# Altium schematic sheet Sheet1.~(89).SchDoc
size A3; SheetNumber: 1; SheetTotal: 1
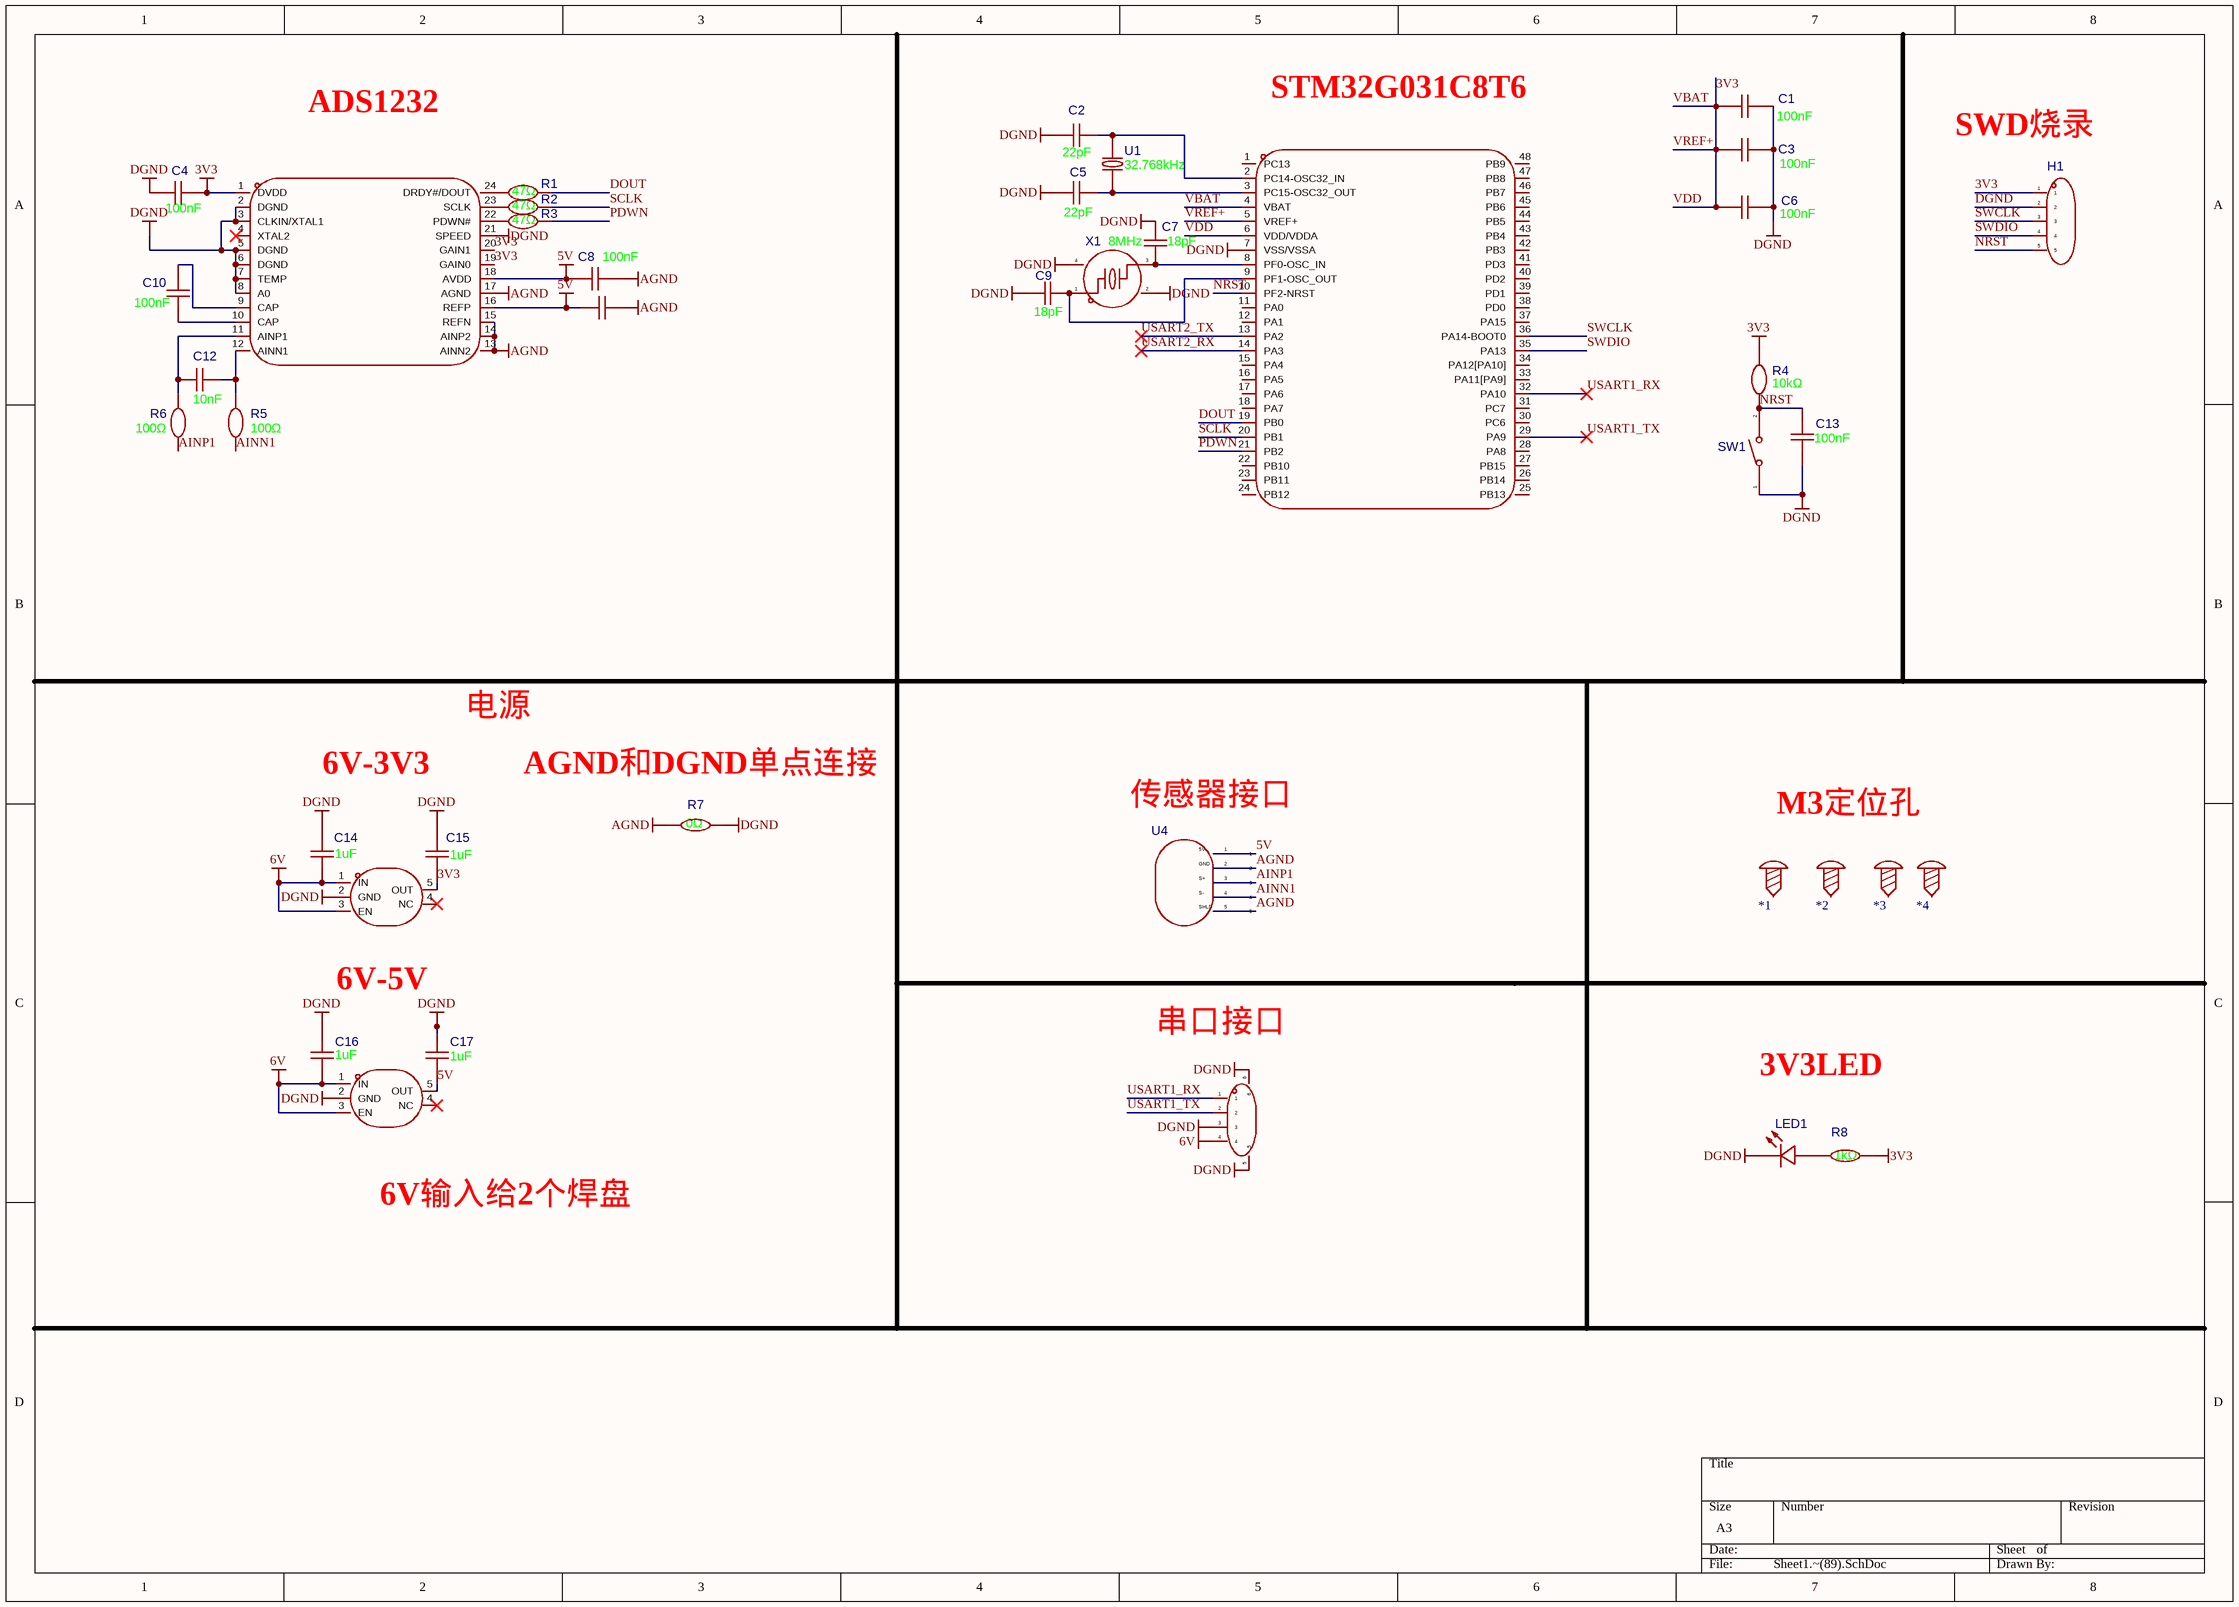
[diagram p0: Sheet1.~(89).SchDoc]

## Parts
*1  螺丝孔_1  [M3螺丝]  (value not drawn)
*2  螺丝孔_1  [M3螺丝]  (value not drawn)
*3  螺丝孔_1  [M3螺丝]  (value not drawn)
*4  螺丝孔_1  [M3螺丝]  (value not drawn)
C1  value 100nF  [C0402]  (hidden comment: cc0402krx7r7bb104)
C2  value 22pF  [C0402]  (hidden comment: cc0402jrnpo9bn220)
C3  value 100nF  [C0402]  (hidden comment: cc0402krx7r7bb104)
C4  value 100nF  [C0402]  (hidden comment: cc0402krx7r7bb104)
C5  value 22pF  [C0402]  (hidden comment: cc0402jrnpo9bn220)
C6  value 100nF  [C0402]  (hidden comment: cc0402krx7r7bb104)
C7  value 18pF  [C0402]  (hidden comment: cc0402jrnpo9bn180)
C8  value 100nF  [C0402]  (hidden comment: cc0402krx7r7bb104)
C9  value 18pF  [C0402]  (hidden comment: cc0402jrnpo9bn180)
C10  value 100nF  [C0402]  (hidden comment: cc0402krx7r7bb104)
C11  cl21b103kbannnc  [C0805]  (value not drawn)
C12  value 10nF  [C0805]  (hidden comment: cl21b103kbannnc)
C13  value 100nF  [C0402]  (hidden comment: cc0402krx7r7bb104)
C14  value 1uF  [C0603]  (hidden comment: cga0603x5r105k500jt)
C15  value 1uF  [C0603]  (hidden comment: cga0603x5r105k500jt)
C16  value 1uF  [C0603]  (hidden comment: cga0603x5r105k500jt)
C17  value 1uF  [C0603]  (hidden comment: cga0603x5r105k500jt)
H1  pz254v-11-05p  [HDR-TH_5P-P2.54-V-M]  (value not drawn)
LED1  ltst-c190kskt  [LED0603-RD]  (value not drawn)
R1  value 47Ω  [R0402]  (hidden comment: frc0402f47r0ts)
R2  value 47Ω  [R0402]  (hidden comment: frc0402f47r0ts)
R3  value 47Ω  [R0402]  (hidden comment: frc0402f47r0ts)
R4  value 10kΩ  [R0603]  (hidden comment: frc0603f1002ts)
R5  value 100Ω  [R0603]  (hidden comment: frc0603f1000ts)
R6  value 100Ω  [R0603]  (hidden comment: frc0603f1000ts)
R7  value 0Ω  [R0603]  (hidden comment: 0603waf0000t5e)
R8  value 1kΩ  [R0603]  (hidden comment: 0603waf1001t5e)
SW1  ts-1088-ar02016  [SW-SMD_L3.9-W3.0-P4.45]  (value not drawn)
U1  value 32.768kHz  [CRYSTAL-SMD_L3.2-W1.5]  (hidden comment: fc31m2-32.768-ntlnndtl)
U2  ads1232ipwr  [TSSOP-24_L7.8-W4.4-P0.65-LS6.4-BL]  (value not drawn)
U3  stm32g031c8t6  [LQFP-48_L7.0-W7.0-P0.50-LS9.0-BL]  (value not drawn)
U4  5个焊盘  [5个焊盘 - duplicate]  (value not drawn)
U5  tps7a2033pdbvr  [SOT-23-5_L2.9-W1.6-P0.95-LS2.8-BR]  (value not drawn)
U6  tps7a2050pdbvr  [SOT-23-5_L2.9-W1.6-P0.95-LS2.8-BR]  (value not drawn)
U7  bx-xh2.54-4pwt  [CONN-SMD_4P-P2.50_BX-XH2.54-4PWT]  (value not drawn)
X1  value 8MHz  [CRYSTAL-SMD_4P-L3.2-W2.5-BL]  (hidden comment: x32258mob4si)

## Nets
3V3: C1.1 C3.1 C4.2 C6.1 C15.1 H1.1 R4.2 R8.2 U2.1(DVDD) U2.19(GAIN0) U2.20(GAIN1) U3.4(VBAT) U3.5(VREF+) U3.6(VDD/VDDA) U5.5(OUT)  [also labelled VBAT, VDD, VREF+]
5V: C8.1 C11.1 C17.1 U2.16(REFP) U2.18(AVDD) U4.1 U6.5(OUT)
6V: C14.1 C16.1 U5.1(IN) U5.3(EN) U6.1(IN) U6.3(EN) U7.4
AGND: C8.2 C11.2 R7.1 U2.13(AINN2) U2.14(AINP2) U2.15(REFN) U2.17(AGND) U4.2 U4.5
DGND: C1.2 C2.1 C3.2 C4.1 C5.1 C6.2 C7.2 C9.1 C13.1 C14.2 C15.2 C16.2 C17.2 H1.2 LED1.1(-) R7.2 SW1.1 U2.2(DGND) U2.3(CLKIN/XTAL1) U2.5(DGND) U2.6(DGND) U2.7(TEMP) U2.8(A0) U2.21(SPEED) U3.7(VSS/VSSA) U5.2(GND) U6.2(GND) U7.3 U7.5 U7.6 X1.2(GND) X1.4(GND)
AINN1: R5.1 U4.4
AINP1: R6.1 U4.3
DOUT: R1.2 U3.19(PB0)
NRST: C13.2 H1.5 R4.1 SW1.2 U3.10(PF2-NRST)
PDWN: R3.2 U3.21(PB2)
SCLK: R2.2 U3.20(PB1)
SWCLK: H1.3 U3.36(PA14-BOOT0)
SWDIO: H1.4 U3.35(PA13)
USART1_RX: U3.32(PA10) U7.1
USART1_TX: U3.29(PA9) U7.2
USART2_RX: U3.14(PA3)
USART2_TX: U3.13(PA2)
NetC2_2: C2.2 U1.2 U3.2(PC14-OSC32_IN)
NetC5_2: C5.2 U1.1 U3.3(PC15-OSC32_OUT)
NetC7_1: C7.1 U3.8(PF0-OSC_IN) X1.3
NetC9_2: C9.2 U3.9(PF1-OSC_OUT) X1.1
NetC10_1: C10.1 U2.10(CAP)
NetC10_2: C10.2 U2.9(CAP)
NetC12_1: C12.1 R6.2 U2.11(AINP1)
NetC12_2: C12.2 R5.2 U2.12(AINN1)
NetLED1_2: LED1.2(+) R8.1
NetR1_1: R1.1 U2.24(DRDY#/DOUT)
NetR2_1: R2.1 U2.23(SCLK)
NetR3_1: R3.1 U2.22(PDWN#)

Not connected (* = marked no-connect by the designer): *1 1; *2 1; *3 1; *4 1; U2 4(XTAL2)*; U3 1(PC13) 11(PA0) 12(PA1) 15(PA4) 16(PA5) 17(PA6) 18(PA7) 22(PB10) 23(PB11) 24(PB12) 25(PB13) 26(PB14) 27(PB15) 28(PA8) 30(PC6) 31(PC7) 33(PA11[PA9]) 34(PA12[PA10]) 37(PA15) 38(PD0) 39(PD1) 40(PD2) 41(PD3) 42(PB3) 43(PB4) 44(PB5) 45(PB6) 46(PB7) 47(PB8) 48(PB9); U5 4(NC)*; U6 4(NC)*

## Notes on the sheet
- ADS1232
- STM32G031C8T6
- (near H1) SWD烧录
- 电源
- 6V-3V3
- (near R7) AGND和DGND单点连接
- (near U4) 传感器接口
- M3定位孔
- 6V-5V
- (near U7) 串口接口
- 3V3LED
- 6V输入给2个焊盘

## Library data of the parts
C1 C3 C4 C6 C8 C10 C13 = cc0402krx7r7bb104: 容值:100nF;精度:±10%;额定电压:16V;温度系数:X7R;; Manufacturer: YAGEO(国巨); AddInBom: yes; ModelId: 36a51122f27c49738f86b3bfa98863e0; ModelName: C0402_L1.0-W0.5-H0.5; ModelTransform: 39.37,19.685,0,0,0,0,0,0,0; Tolerance: ±10%; Voltage Rating: 16V; Temperature Coefficient: X7R
C2 C5 = cc0402jrnpo9bn220: 容值:22pF;精度:±5%;额定电压:50V;温度系数:NP0;; Manufacturer: YAGEO(国巨); AddInBom: yes; ModelId: 36a51122f27c49738f86b3bfa98863e0; ModelName: C0402_L1.0-W0.5-H0.5; ModelTransform: 39.37,19.685,0,0,0,0,0,0,0; Tolerance: ±5%; Voltage Rating: 50V; Temperature Coefficient: NP0
C7 C9 = cc0402jrnpo9bn180: 容值:18pF;精度:±5%;额定电压:50V;温度系数:NP0;; Manufacturer: YAGEO(国巨); AddInBom: yes; ModelId: 36a51122f27c49738f86b3bfa98863e0; ModelName: C0402_L1.0-W0.5-H0.5; ModelTransform: 39.37,19.685,0,0,0,0,0,0,0; Tolerance: ±5%; Voltage Rating: 50V; Temperature Coefficient: NP0
C11 = cl21b103kbannnc: 容值:10nF;精度:±10%;额定电压:50V;温度系数:X7R;; Manufacturer: SAMSUNG(三星); AddInBom: yes; ModelId: 1ba041120af144c991958decab20d241; ModelName: C0805_L2.0-W1.3-H1.3; ModelTransform: 78.74,51.181,0,0,0,0,0,0.0005,0; Value: 10nF; Tolerance: ±10%; Voltage Rating: 50V; Temperature Coefficient: X7R
C12 = cl21b103kbannnc: 容值:10nF;精度:±10%;额定电压:50V;温度系数:X7R;; Manufacturer: SAMSUNG(三星); AddInBom: yes; ModelId: 1ba041120af144c991958decab20d241; ModelName: C0805_L2.0-W1.3-H1.3; ModelTransform: 78.74,51.181,0,0,0,0,0,0.0005,0; Tolerance: ±10%; Voltage Rating: 50V; Temperature Coefficient: X7R
C14-C17 = cga0603x5r105k500jt: 容值:1uF;精度:±10%;额定电压:50V;温度系数:X5R;; Manufacturer: HRE(芯声); AddInBom: yes; ModelId: ac125912035d415993ca9572d50418b1; ModelName: C0603_L1.6-W0.8-H0.8; ModelTransform: 62.992,31.496,0,0,0,0,0,0,0; Tolerance: ±10%; Voltage Rating: 50V; Temperature Coefficient: X5R
H1 = pz254v-11-05p: 插针结构:1x5P;间距:2.54mm;行距:-;圆针/方针:方针;安装方式:直插;排数:单排;总PIN位数:5P;额定电流:3A;额定电压:250V;配合针长度:6mm;塑高:2.5mm;端接针长度:3mm;触头材质:黄铜;触头镀层:-;工作温度:-40℃~+105℃;颜色:黑色;; Manufacturer: XFCN(兴飞); AddInBom: yes; ModelId: 47d466e4a34f4fc5bc626cf773a24dd5; ModelName: HDR-TH_5P-P2.54-M-LI-1X5P; ModelTransform: 499.999,100,0,0,0,0,0,0,-118.11; Pin Structure: 1x5P; Pitch: 2.54mm; Circluar Pins/Square Pins: 方针; Current Rating: 3A; Voltage Rating (Max): 250V
LED1 = ltst-c190kskt: 灯头类型:-;发光颜色:黄色;正向压降(Vf):2.1V;功率:75mW;正向电流:20mA;波长:584.5nm~597nm;二极管配置:独立二极管;透镜颜色:无色透明透镜;色温:-;发光强度:104mcd;发光角度:130°;载带方式:-;工作温度:-30℃~+85℃;; Manufacturer: LITEON(光宝); AddInBom: yes; ModelId: 1f0d29a91be547639d425604e9b96ebb; ModelTransform: 63.7794,32.283,0,0,0,0,0,0,0; Illumination Color: 黄色; Voltage - Forward(Vf): 2.1V; Power(Watts): 75mW; Forward Current: 20mA; Peak Wavelength: 588nm; Diode Configuration: 独立二极管; Lens Color: 无色透明透镜; Luminous Intensity: 104mcd; Viewing Angle: 130°
R1-R3 = frc0402f47r0ts: 电阻类型:厚膜电阻;阻值:47Ω;精度:±1%;功率:62.5mW;工作电压:50V;温度系数:±100ppm/℃;; Manufacturer: FOJAN(富捷); AddInBom: yes; ModelId: 98c88bc2b9094f218f3a3e30a7012738; ModelName: R0402_L1.0-W0.5-H0.4; ModelTransform: 39.37,19.685,0,0,0,0,0,0,0; Tolerance: ±1%; Power(Watts): 62.5mW; Voltage-Supply(Max): 50V
R4 = frc0603f1002ts: 电阻类型:厚膜电阻;阻值:10kΩ;精度:±1%;功率:100mW;工作电压:75V;温度系数:±100ppm/℃;; Manufacturer: FOJAN(富捷); AddInBom: yes; ModelId: fc143cca1e79419f9cd78b61e9279f08; ModelTransform: 31.8897,63.7794,0,90,0,0,0,0,0; Tolerance: ±1%; Power(Watts): 100mW; Voltage-Supply(Max): 75V
R5 R6 = frc0603f1000ts: 电阻类型:厚膜电阻;阻值:100Ω;精度:±1%;功率:100mW;工作电压:75V;温度系数:±100ppm/℃;; Manufacturer: FOJAN(富捷); AddInBom: yes; ModelId: fc143cca1e79419f9cd78b61e9279f08; ModelTransform: 31.8897,63.7794,0,90,0,0,0,0,0; Tolerance: ±1%; Power(Watts): 100mW; Voltage-Supply(Max): 75V
R7 = 0603waf0000t5e: 电阻类型:厚膜电阻;阻值:0Ω;精度:±1%;功率:100mW;工作电压:75V;温度系数:-;; Manufacturer: UNI-ROYAL(厚声); AddInBom: yes; ModelId: fc143cca1e79419f9cd78b61e9279f08; ModelTransform: 31.8897,63.7794,0,90,0,0,0,0,0; Tolerance: ±1%; Power(Watts): 100mW; Voltage-Supply(Max): 75V
R8 = 0603waf1001t5e: 电阻类型:厚膜电阻;阻值:1kΩ;精度:±1%;功率:100mW;工作电压:75V;温度系数:±100ppm/℃;; Manufacturer: UNI-ROYAL(厚声); AddInBom: yes; ModelId: fc143cca1e79419f9cd78b61e9279f08; ModelTransform: 31.8897,63.7794,0,90,0,0,0,0,0; Tolerance: ±1%; Power(Watts): 100mW; Voltage-Supply(Max): 75V
SW1 = ts-1088-ar02016: 电路结构:单刀单掷;按钮形状:圆形按钮;作用力:1.6N;安装方式:立贴;开关长度:3.9mm;开关宽度:3mm;开关高度:2mm;带支架:不带支架;触点电流:50mA;额定电压:12V;带灯:-;工作寿命:10万次;; Manufacturer: XUNPU(讯普); AddInBom: yes; ModelId: b26698b69f274ffabef8a26c7d0e5dd1; ModelName: SW-SMD_L3.9-W2.9-H2.0-LS4.8; ModelTransform: 188.976,114.174,0,0,0,0,0,0,0; Circuit: 单刀单掷; Actuator Style: 圆形按钮; Operating Force: 1.6N; Switch Height: 2mm; with Bracket: 不带支架; Contact Current: 50mA; Voltage Rating: 12V; Actuator/Cap Color: 黑色; Life: 10万次
U1 = fc31m2-32.768-ntlnndtl: 晶振类型:贴片晶振;频率:32.768kHz;常温频差:±10ppm;负载电容:12.5pF;频率稳定度:±10ppm;; Manufacturer: HCI(杭晶); AddInBom: yes; ModelId: 762d7afc596f4558a373612390f4386d; ModelName: CRYSTAL-SMD_L3.2-W1.5-1; ModelTransform: 125.984,59.055,0,0,0,0,0,0,0; Normal temperature Frequency Tolerance: ±10ppm; Load Capacitance: 12.5pF; Equivalent Series Resistance(ESR): 70kΩ
U2 = ads1232ipwr: 分辨率(位):24;采样率:10Hz;工作电压:2.7V~5.3V;接口类型:SPI;; Manufacturer: TI(德州仪器); AddInBom: yes; ModelId: 57e278220af748a2882c4abba4094eb9; ModelName: TSSOP-24_L7.8-W4.4-H1.0-LS6.4-P0.65; ModelTransform: 252.188,307.086,0,90,0,0,0,0,0; Resolution (Bits): 24; Sampling Rate: 10Hz; number of channels: 2; Interface: SPI; differential input: 是; Clock/Oscillator: 内置；外置; Clock Frequency: 4.9152MHz；200kHz~8MHz; Voltage Reference: 外置; Programmable Gain: 支持; Temperature Sensors: 内置; ADC architecture: Sigma-Delta; Data rate: 80Hz；10Hz; Quiescent Current (Iq): 1.3uA; Full-Scale Range(FSR): 39mV；1.25V；19.5mV；2.5V
U3 = stm32g031c8t6: CPU内核:ARM Cortex-M0+;CPU最大主频:64MHz;CPU位数:32 Bit;; Manufacturer: ST(意法半导体); AddInBom: yes; ModelId: 093be70396ff421eb2cdb946d5311efc; ModelName: LQFP-48_L7.0-W7.0-H1.4-LS9.0-P0.50; ModelTransform: 354.331,354.331,0,0,0,0,0,0,0; CPU Maximum Speed: 64MHz; Core Size: 32 Bit; Program Storage Size: 64KB; Program Memory Type: FLASH; RAM Size: 8KB; Number of I/O: 44; ADC (Bit): 12bit; Oscillator Type: 内置+外置; Voltage - Supply: 1.7V~3.6V
U4 = 5个焊盘: Convert to PCB: yes
U5 = tps7a2033pdbvr: 输出类型:固定;最大输入电压:6V;输出电压:3.3V;输出电流:300mA;输出极性:正极;; Manufacturer: TI(德州仪器); AddInBom: yes; ModelId: 7ba65df16e7b4570af156e925f9c37fe; ModelTransform: 114.173,114.173,0,90,0,0,0,0,0; Output Type: 固定; Maximum Input Voltage: 6V; Output Voltage: 3.3V; Output Current: 300mA; Dropout Voltage: 140mV@(300mA); standby current: 15uA; Output Polarity: 正极; Number of Outputs: 1
U6 = tps7a2050pdbvr: 输出极性:正极;工作电压:6V;输出电压:5V;输出电流:300mA;电源纹波抑制比(PSRR):65dB@(100Hz);输出类型:固定;; Manufacturer: TI(德州仪器); AddInBom: yes; ModelId: 7ba65df16e7b4570af156e925f9c37fe; ModelTransform: 114.173,114.173,0,90,0,0,0,0,0; Output Configuration: 正极; Voltage - Supply: 6V; Output Voltage: 5V; Output Current: 300mA; Voltage Dropout: 140mV@(300mA); standby current: 6.5uA; Noise: 10uVrms; Output Type: 固定; Number of Outputs: 1
U7 = bx-xh2.54-4pwt: 插针结构:1x4P;间距:2.5mm;安装方式:卧贴;参考系列:XH;总PIN数:4P;排数:1;每排PIN数:4;行距:-;额定电流:3A;触头材质:黄铜;触头镀层:锡;工作温度:-25℃~+85℃;; Manufacturer: Bossie(博锡); AddInBom: yes; ModelId: fc4292fdbd0c45d68488b12ac9a84ffb; ModelTransform: 590.55,413.385,0,0,0,0,-0.003,-11.339,0; Pins Structure: 1x4P; Pitch: 2.5mm; Reference Series: XH; Number of PINs Per Row: 4; Current Rating: 3A; Voltage Rating: 250V; Supplementary Features: 辅助焊脚; Z-Height of the Board: 6.2mm; X-Length of Bottom Edge on Board (Spacing Line): 15mm; Y-Width of Bottom Edge on Board: 10.5mm
X1 = x32258mob4si: 晶振类型:贴片晶振;频率:8MHz;常温频差:±10ppm;负载电容:12pF;频率稳定度:±20ppm;; Manufacturer: YXC(扬兴晶振); AddInBom: yes; ModelId: ff2dfd5650294453a14147960efe1838; ModelTransform: 125.984,98.425,0,0,0,0,0,0,0; Normal temperature Frequency Tolerance: ±10ppm; Load Capacitance: 12pF; Frequency Stability: ±20ppm; Equivalent Series Resistance(ESR): 180Ω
